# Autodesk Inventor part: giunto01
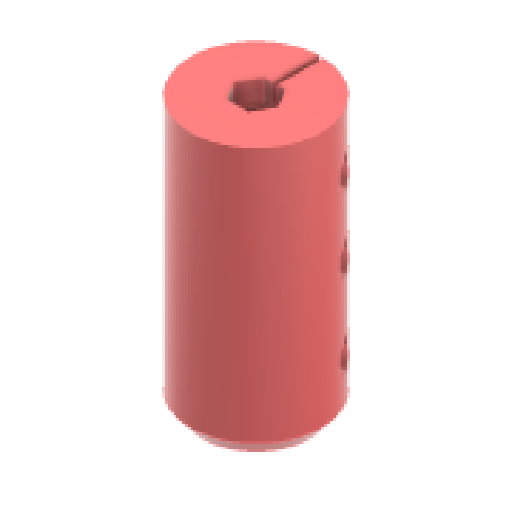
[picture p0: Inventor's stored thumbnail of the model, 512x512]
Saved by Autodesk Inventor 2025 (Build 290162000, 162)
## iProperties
Created: 2025-04
Part Number: giunto01
Material: Generico
Document SubType Name: Modeling
Designer: R5800u
Density: 1 g/cm^3
Appearance: Liscia - Rosso
Author: R5800u
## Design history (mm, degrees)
sketch "Schizzo1"
  geometry: L1 (0, 0)-(10, 0); L2 (10, 0)-(14, 5); L3 (14, 5)-(14, 60); L4 (14, 60)-(0, 60); L5 (0, 60)-(0, 0); L6 (2.55, 60)-(2.55, 0)
  constraints: 12 end point, 3 perpendicular, 2 point on line, 1 horizontal, 1 vertical
  dimensions: "d0" = 10 distance of L1.start L1.end; "d2" = 14 horizontal distance of L1.start L2.end; "d4" = 60 distance from line of L1.start L4; "d5" = 55 distance of L2.end L3.end; "d6" = 2.55 distance between parallel lines of L5 L6
revolve "Rivoluzione1" sketch "Schizzo1" stored, may be unused: angle "d7" = 360 deg
chamfer "Smusso1" distance "d9" = 2; stored, may be unused: second distance "d10" = 2, angle "d11" = 45 deg
sketch "Schizzo2" dims "d12" = 9.4
  geometry: L1 (4.7, 0)-(2.35, -4.07); L2 (2.35, -4.07)-(-2.35, -4.07); L3 (-2.35, -4.07)-(-4.7, 0); L4 (-4.7, 0)-(-2.35, 4.07); L5 (-2.35, 4.07)-(2.35, 4.07); L6 (2.35, 4.07)-(4.7, 0); C1 r 2.55 at (0, 0) reference; 3 further points
  constraints: 12 end point, 2 coincident, 1 horizontal alignment, 15 other
extrude "Estrusione1" cut sketch "Schizzo2" distance "d13" = 5; taper "d14" = 0 deg
sketch "Schizzo3"
  geometry: L1 (0.5, -15.762)-(-0.5, -15.762); L2 (-0.5, -15.762)-(-0.5, 15.762); L3 (-0.5, 15.762)-(0.5, 15.762); L4 (0.5, 15.762)-(0.5, -15.762); L5 (0.5, -15.762)-(-0.5, 15.762); L6 (-0.5, -15.762)-(0.5, 15.762); C1 r 2.55 at (0, 0) reference; C2 r 2.55 at (0, 0) reference; 3 further points
  constraints: 12 end point, 2 midpoint, 2 parallel, 1 horizontal, 1 perpendicular
  dimensions: "d15" = 1 distance of L2.end L3.end
extrude "Estrusione2" cut sketch "Schizzo3" extent not by distance; stored distance "d16" = 0; taper "d17" = 0 deg
sketch "Schizzo4"
  geometry: L1 (60, -13.991)-(60, -4.07) reference; L2 (60, -8)-(0.939, -8); C1 r 1.6 at (14, -8); C2 r 1.6 at (32, -8); C3 r 1.6 at (48, -8); 4 further points
  constraints: 4 point on line, 3 centre point, 3 coincident, 2 end point, 1 horizontal
  dimensions: "d18" = 8 distance from line of point (0, 0) L2; "d19" = 14 horizontal distance of point (0, 0) point (14, -8); "d20" = 18 distance of point (14, -8) point (32, -8); "d21" = 12 distance from line of L1 point (48, -8); "d22" = 3.2 diameter of C1; "d23" = 3.2 diameter of C2; "d24" = 3.2 diameter of C3
extrude "Estrusione3" cut sketch "Schizzo4" extent not by distance; stored distance "d25" = 0; taper "d26" = 0 deg
node "Piano di lavoro1"
node "Piano di lavoro2"
sketch "Schizzo5"
  geometry: L1 (11.005, 13.777)-(8.011, 12.036); L2 (8.011, 12.036)-(5.005, 13.759); L3 (5.005, 13.759)-(4.995, 17.223); L4 (4.995, 17.223)-(7.989, 18.964); L5 (7.989, 18.964)-(10.995, 17.241); L6 (10.995, 17.241)-(11.005, 13.777); L7 (11.012, -2.212)-(8.023, -3.964); L8 (8.023, -3.964)-(5.012, -2.252); L9 (5.012, -2.252)-(4.988, 1.212); L10 (4.988, 1.212)-(7.977, 2.964); L11 (7.977, 2.964)-(10.988, 1.252); L12 (10.988, 1.252)-(11.012, -2.212); L13 (11.014, -20.208)-(8.028, -21.964); L14 (8.028, -21.964)-(5.014, -20.256); L15 (5.014, -20.256)-(4.986, -16.792); L16 (4.986, -16.792)-(7.972, -15.036); L17 (7.972, -15.036)-(10.986, -16.744); L18 (10.986, -16.744)-(11.014, -20.208); C1 r 1.6 at (8, 15.5) reference; C2 r 1.6 at (8, -0.5) reference; C3 r 1.6 at (8, -18.5) reference; 4 further points
  constraints: 36 end point, 3 coincident, 39 other
  dimensions: "d27" = 6 distance between parallel lines of L3 L6; "d28" = 6 distance between parallel lines of L9 L12; "d29" = 6 distance between parallel lines of L15 L18
extrude "Estrusione4" cut sketch "Schizzo5" distance "d30" = 7; taper "d31" = 0 deg
sketch "Schizzo6"
  geometry: C1 r 1.6 at (-8, -18.5) reference; C2 r 2.75 at (-8, -18.5); C3 r 1.6 at (-8, -0.5) reference; C4 r 2.75 at (-8, -0.5); C5 r 1.6 at (-8, 15.5) reference; C6 r 2.75 at (-8, 15.5); 1 further point
  constraints: 3 centre point, 3 coincident
  dimensions: "d32" = 5.5 diameter of C2; "d33" = 5.5 diameter of C4; "d34" = 5.5 diameter of C6
extrude "Estrusione5" cut sketch "Schizzo6" distance "d35" = 6; taper "d36" = 0 deg
node "Solido1"
